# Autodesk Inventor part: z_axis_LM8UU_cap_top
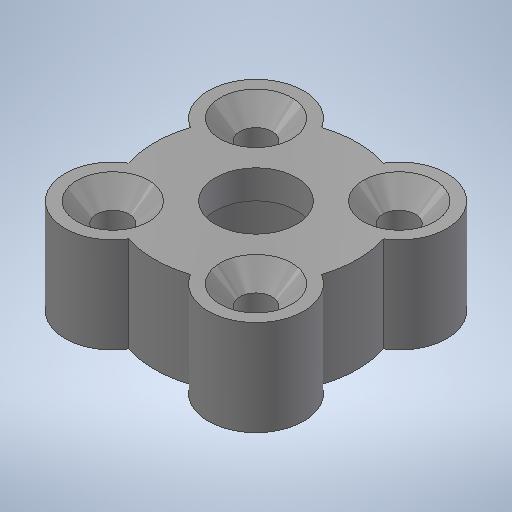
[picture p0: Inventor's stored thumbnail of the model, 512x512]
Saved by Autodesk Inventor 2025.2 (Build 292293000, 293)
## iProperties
Created: 2025-04
Part Number: z_axis_LM8UU_cap_top
Material: 1.0037 S235JR
Document SubType Name: Modeling
Designer: BennF
Density: 7.85 g/cm^3
Appearance: Stahl
Author: BennF
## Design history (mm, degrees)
sketch "Sketch2"
  geometry: L1 (-7.625, 7)-(-7.625, 0); L2 (-7.625, 0)-(-10.625, 0); L3 (-10.625, 0)-(-10.625, 10); L4 (0, 0)-(0, 10); L5 (-7.625, 7)-(-4.25, 7); L6 (-4.25, 7)-(-4.25, 10); L7 (-4.25, 10)-(-10.625, 10)
  constraints: 14 end point, 3 perpendicular, 2 horizontal, 2 horizontal alignment, 1 vertical
  dimensions: "d0" = 15.25 diameter of L1 L4; "d1" = 8.5 diameter of L6 L4; "d2" = 7 distance of L1.start L1.end; "d3" = 3 distance of L5.end L6.end; "d4" = 3 distance of L1.end L2.end
revolve "Revolution1" sketch "Sketch2" stored, may be unused: angle "d5" = 90 deg
sketch "Sketch3"
  geometry: L1 (-7.513, 7.513)-(7.513, -7.513); L2 (7.513, 7.513)-(-7.513, -7.513); A1 r 5 centre (-7.513, 7.513) between (-3.245, 10.117) and (-10.117, 3.245); A2 r 5 centre (7.513, 7.513) between (10.117, 3.245) and (3.245, 10.117); A3 r 5 centre (7.513, -7.513) between (3.245, -10.117) and (10.117, -3.245); A4 r 5 centre (-7.513, -7.513) between (-10.117, -3.245) and (-3.245, -10.117); 3 further points
  constraints: 8 point on circle, 4 centre point, 4 end point, 3 equal radius, 2 midpoint, 1 coincident, 1 horizontal alignment, 1 perpendicular, 13 other
  dimensions: "d6" = 5 radius of A1
extrude "Extrusion1" join sketch "Sketch3" stored distance "d7" = 5; taper "d8" = 0 deg
sketch "Sketch4"
  geometry: A1 r 5 centre (7.513, -7.513) between (3.245, -10.117) and (10.117, -3.245) reference; A2 r 5 centre (-7.513, -7.513) between (-10.117, -3.245) and (-3.245, -10.117) reference; A3 r 5 centre (-7.513, 7.513) between (-3.245, 10.117) and (-10.117, 3.245) reference; A4 r 5 centre (7.513, 7.513) between (10.117, 3.245) and (3.245, 10.117) reference; 5 further points
  constraints: 4 coincident
hole "Hole1" sketch "Sketch4" at (7.513, -7.513), (-7.513, -7.513), (-7.513, 7.513), (7.513, 7.513) diameter "d9" = 3.4; stored, may be unused: countersink angle "d13" = 90 deg, drill point angle "d15" = 118 deg; dims "d10" = 6, "d11" = 7.5, "d12" = 2, "d14" = 8
body "Solid1"
